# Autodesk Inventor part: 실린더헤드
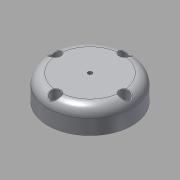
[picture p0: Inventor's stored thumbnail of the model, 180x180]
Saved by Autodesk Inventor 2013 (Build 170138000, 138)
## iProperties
Created: 2016-11
Part Number: 실린더헤드
Material: 알루미늄 6061
Document SubType Name: Modeling
Designer: mduedu
Density: 2.71 g/cm^3
Mass: 284.826 g
Surface Area: 227.25 cm^2
Volume: 105.102 cm^3
Author: mduedu
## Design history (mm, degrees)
sketch "스케치1"
  geometry: C1 r 42.5 at (0, 0); 1 further point
  constraints: 1 centre point, 1 coincident
  dimensions: "d0" = 85 diameter of C1
extrude "돌출1" new body sketch "스케치1" distance "d1" = 25; taper "d2" = 0 deg
fillet "모깎기1" dims "d3" = 10
sketch "스케치2"
  geometry: C1 r 30 at (0, 0); 1 further point
  constraints: 1 centre point, 1 coincident
  dimensions: "d4" = 60 diameter of C1
extrude "돌출2" join sketch "스케치2" distance "d5" = 5; taper "d6" = 0 deg
sketch "스케치3"
  geometry: C1 r 25 at (0, 0); 1 further point
  constraints: 1 centre point, 1 coincident
  dimensions: "d7" = 50 diameter of C1
extrude "돌출3" cut sketch "스케치3" distance "d8" = 20; taper "d9" = 0 deg
hole "구멍1" diameter "d12" = 4.134; stored, may be unused: countersink angle "d16" = 90 deg, drill point angle "d18" = 118 deg; dims "d10" = 10, "d11" = 10, "d13" = 6, "d14" = 4, "d15" = 2, "d17" = 8
chamfer "모따기1" distance "d19" = 1; stored, may be unused: second distance "d20" = 2, angle "d21" = 45 deg
fillet "모깎기2" dims "d22" = 3
sketch "스케치4"
  geometry: C1 r 17.5 at (0, 0); 1 further point
  constraints: 1 centre point, 1 coincident
  dimensions: "d23" = 35 diameter of C1
extrude "돌출4" cut sketch "스케치4" distance "d24" = 2; taper "d25" = 0 deg
fillet "모깎기3" dims "d26" = 0.5
sketch "스케치5" dims "d32" = 70
  geometry: C1 r 5 at (0, 35); 3 further points
  constraints: 2 coincident, 2 vertical alignment, 1 centre point, 2 other
  dimensions: "d33" = 10 diameter of C1
extrude "돌출5" cut sketch "스케치5" distance "d34" = 10; taper "d35" = 0 deg
sketch "스케치6" dims "d39" = 70
  geometry: 6 further points
  constraints: 2 vertical alignment, 1 coincident, 7 other
  dimensions: "d42" = 360 deg dimension on point (0, -35) point (0, 0) (derived)
sketch "스케치7"
  geometry: 4 further points
  constraints: 4 other
hole "구멍2" sketch "스케치7" at (0, 70), (-35, 35), (35, 35), (0, 0) diameter "d44" = 5.5; stored, may be unused: countersink angle "d48" = 90 deg, drill point angle "d50" = 0 deg; dims "d45" = 6, "d46" = 4, "d47" = 2, "d49" = 8
fillet "모깎기4" dims "d51" = 0.5
node "솔리드1"
pattern_circular "원형 패턴1" dims angle "d37" = 360 deg
